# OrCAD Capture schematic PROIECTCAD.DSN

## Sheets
1 PAGE2: size A3
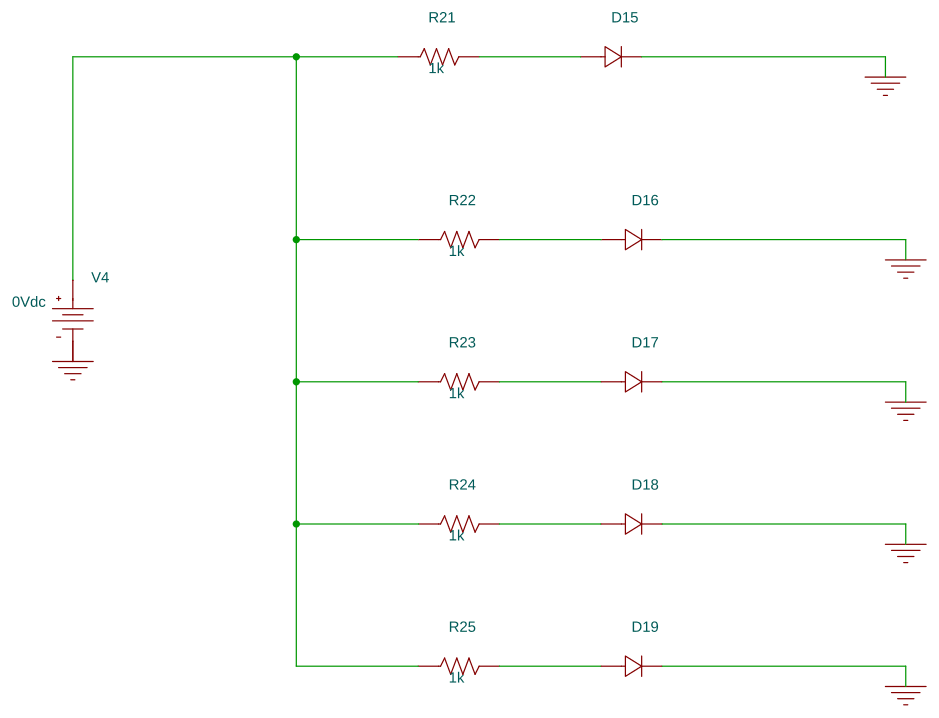
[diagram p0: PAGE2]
2 PAGE1: size A3
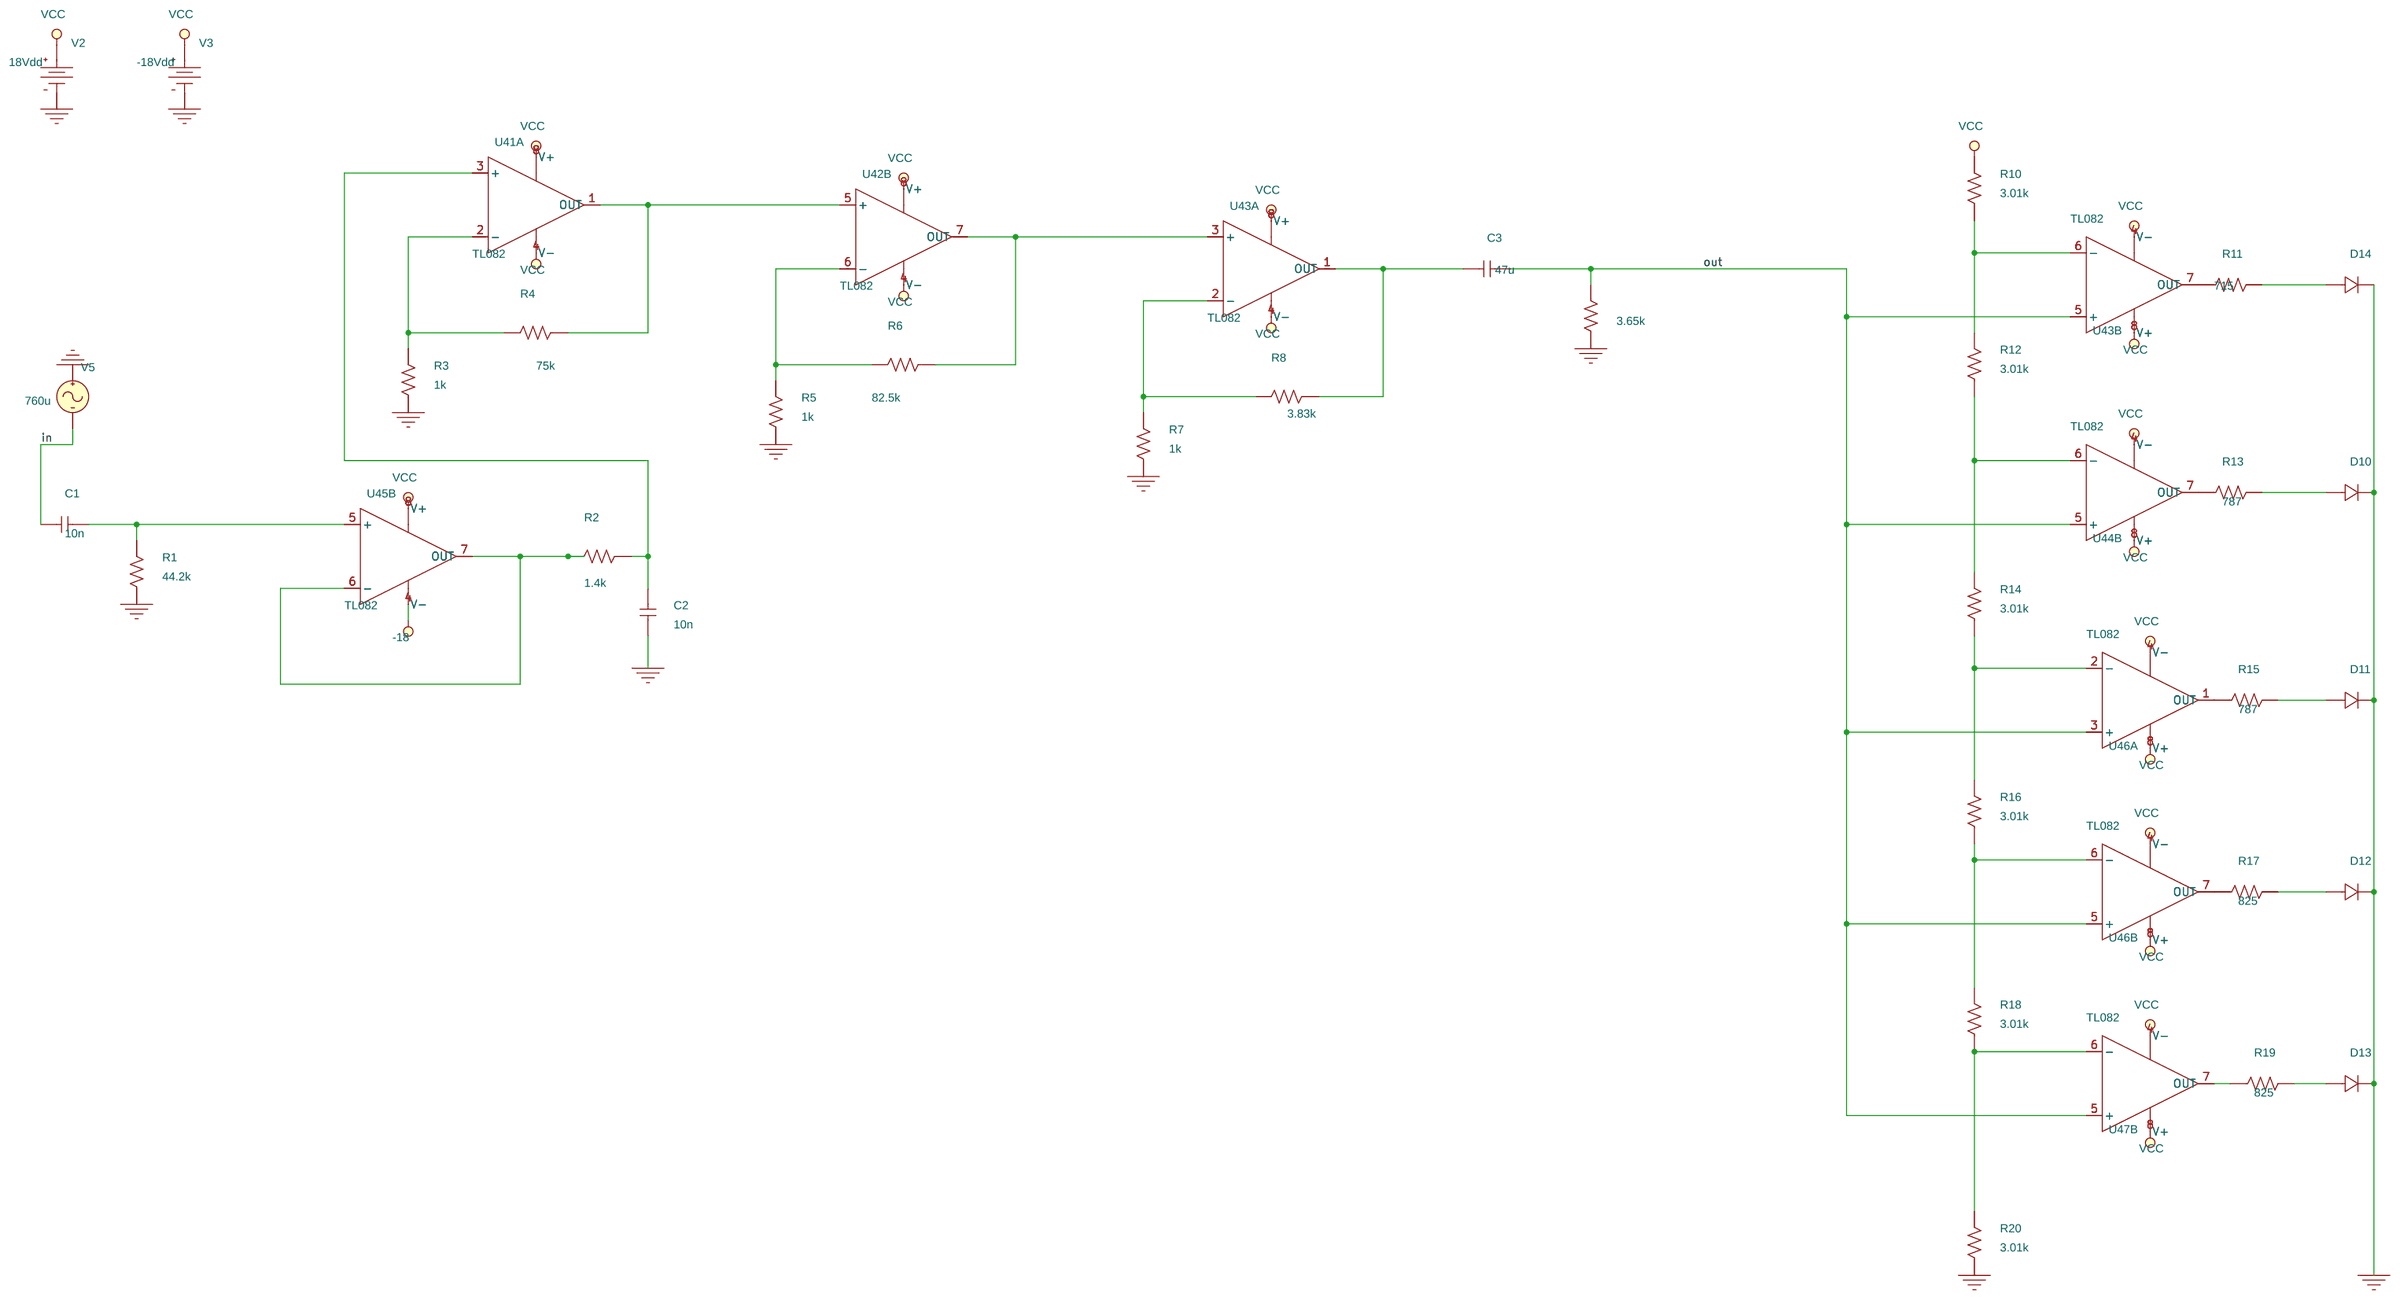
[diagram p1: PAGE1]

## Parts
sheet PAGE1
C1  10n  [RAD/CK05]
C2  10n  [RAD/CK05]
C3  47u  [RAD/CK05]
D10  Dbreak
D11  Dbreak
D12  Dbreak
D13  Dbreak
D14  Dbreak
R1  44.2k  [AX/RC05]
R2  1.4k  [AX/RC05]
R3  1k  [AX/RC05]
R4  75k  [AX/RC05]
R5  1k  [AX/RC05]
R6  82.5k  [AX/RC05]
R7  1k  [AX/RC05]
R8  3.83k  [AX/RC05]
R9  3.65k  [AX/RC05]
R10  3.01k  [AX/RC05]
R11  715  [AX/RC05]
R12  3.01k  [AX/RC05]
R13  787  [AX/RC05]
R14  3.01k  [AX/RC05]
R15  787  [AX/RC05]
R16  3.01k  [AX/RC05]
R17  825  [AX/RC05]
R18  3.01k  [AX/RC05]
R19  825  [AX/RC05]
R20  3.01k  [AX/RC05]
U41  TL082  [DIP.100/8/W.300/L.450]  (section A)
U42  TL082  [DIP.100/8/W.300/L.450]  (section B)
U43  TL082  [DIP.100/8/W.300/L.450]  (sections A,B)
U44  TL082  [DIP.100/8/W.300/L.450]  (section B)
U45  TL082  [DIP.100/8/W.300/L.450]  (section B)
U46  TL082  [DIP.100/8/W.300/L.450]  (sections A,B)
U47  TL082  [DIP.100/8/W.300/L.450]  (section B)
V2  VDC
V3  VDC
V5  VAC
sheet PAGE2
D15  Dbreak
D16  Dbreak
D17  Dbreak
D18  Dbreak
D19  Dbreak
R21  1k  [AX/RC05]
R22  1k  [AX/RC05]
R23  1k  [AX/RC05]
R24  1k  [AX/RC05]
R25  1k  [AX/RC05]
V4  VDC

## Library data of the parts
C1-C3 = C
D10-D19 = Dbreak: PSpiceTemplate: D^@REFDES %1 %2 @MODEL ?AREA/@AREA/
R1-R20 = R: TOLERANCE: 2%
U41-U47 = TL082
V2 = VDC: DC: 18Vdd
V3 = VDC: DC: -18Vdd
V5 = VAC: DC: 760u
R21-R25 = R
V4 = VDC: DC: 0Vdc

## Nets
0: C2.1 D10.1(2) D11.1(2) D12.1(2) D13.1(2) D14.1(2) D15.1(2) D16.1(2) D17.1(2) D18.1(2) D19.1(2) R1.1 R3.1 R5.1 R7.1 R9.1 R20.1 V2.1(-) V3.1(-) V4.1(-) V5.1(+)
+18: R10.2 U41.8(V+) U42.8(V+) U43.8(V+) U44.8(V+) U45.8(V+) U46.8(V+) U47.8(V+) V2.0(+)
-18: U41.4(V-) U42.4(V-) U43.4(V-) U44.4(V-) U45.4(V-) U46.4(V-) U47.4(V-) V3.0(+)
in: C1.1 V5.2(-)
out: C3.2 R9.2 U43.5(+) U44.5(+) U46.3(+) U46.5(+) U47.5(+)
N59850: C2.2 R2.1 U41.3(+)
N59936: R4.1 U41.1(OUT) U42.5(+)
N59994: R10.1 R12.2 U43.6(-)
N60006: R3.2 R4.2 U41.2(-)
N60016: R6.1 U42.7(OUT) U43.3(+)
N60132: R5.2 R6.2 U42.6(-)
N60142: C3.1 R8.1 U43.1(OUT)
N60224: D14.0(1) R11.2
N60244: R7.2 R8.2 U43.2(-)
N60482: R12.1 R14.2 U44.6(-)
N60654: D10.0(1) R13.2
N60716: C1.2 R1.2 U45.5(+)
N60790: R2.2 U45.6(-) U45.7(OUT)
N60892: R14.1 R16.2 U46.2(-)
N61006: D11.0(1) R15.2
N61062: R16.1 R18.2 U46.6(-)
N61154: D12.0(1) R17.2
N61244: R18.1 R20.2 U47.6(-)
N61298: D13.0(1) R19.2
N61603: R21.1 R22.1 R23.1 R24.1 R25.1 V4.0(+)
N62330: D15.0(1) R21.2
N62334: D16.0(1) R22.2
N62338: D17.0(1) R23.2
N62342: D18.0(1) R24.2
N62346: D19.0(1) R25.2
N67152: R19.1 U47.7(OUT)
N67163: R17.1 U46.7(OUT)
N67167: R15.1 U46.1(OUT)
N67171: R13.1 U44.7(OUT)
N67175: R11.1 U43.7(OUT)
